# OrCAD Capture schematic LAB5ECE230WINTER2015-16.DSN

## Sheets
1 bit LCD: size A
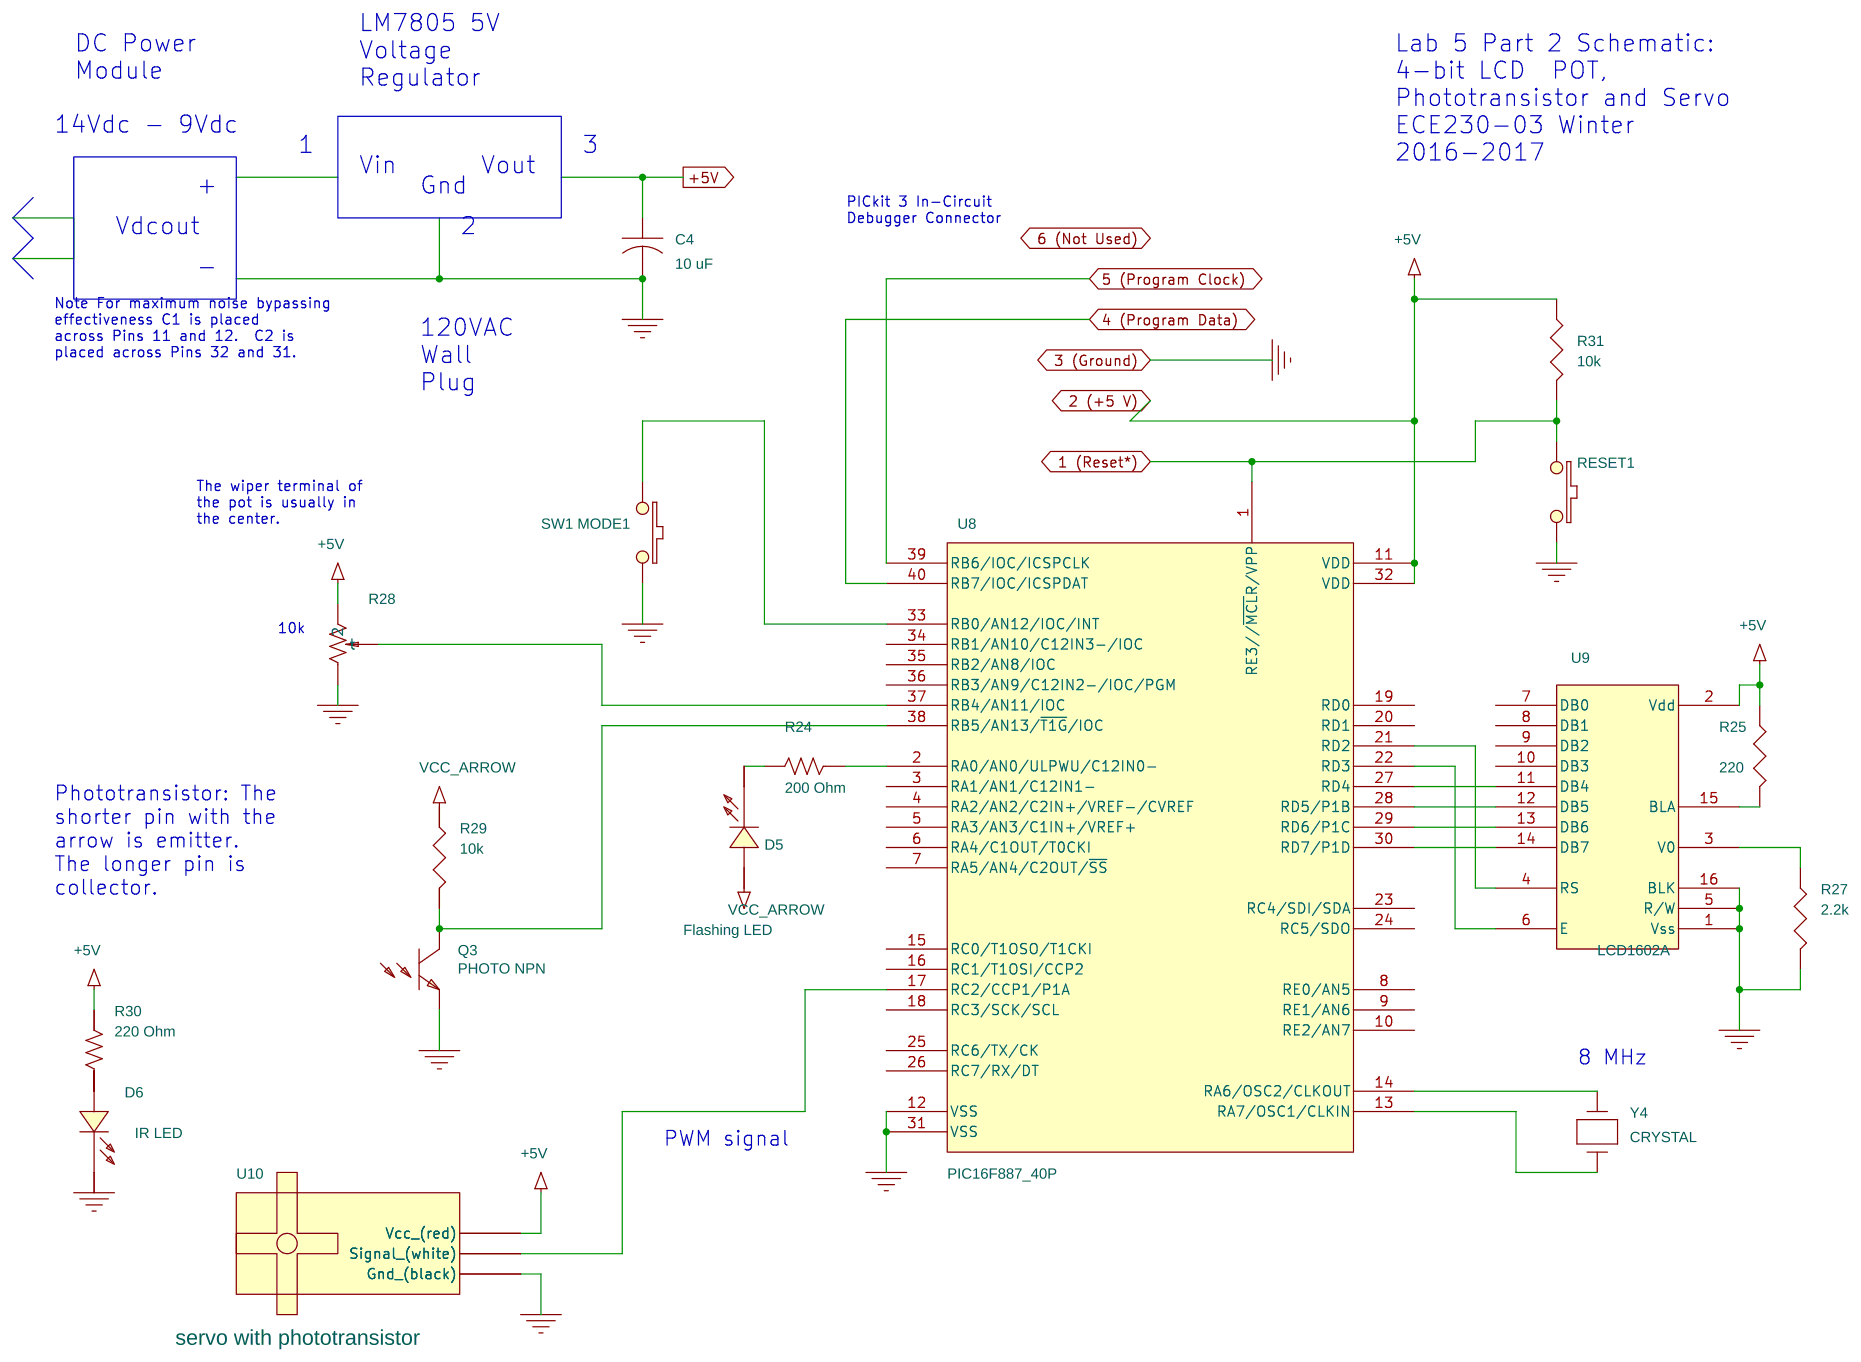
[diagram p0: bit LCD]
2 bit LCD (2): size A
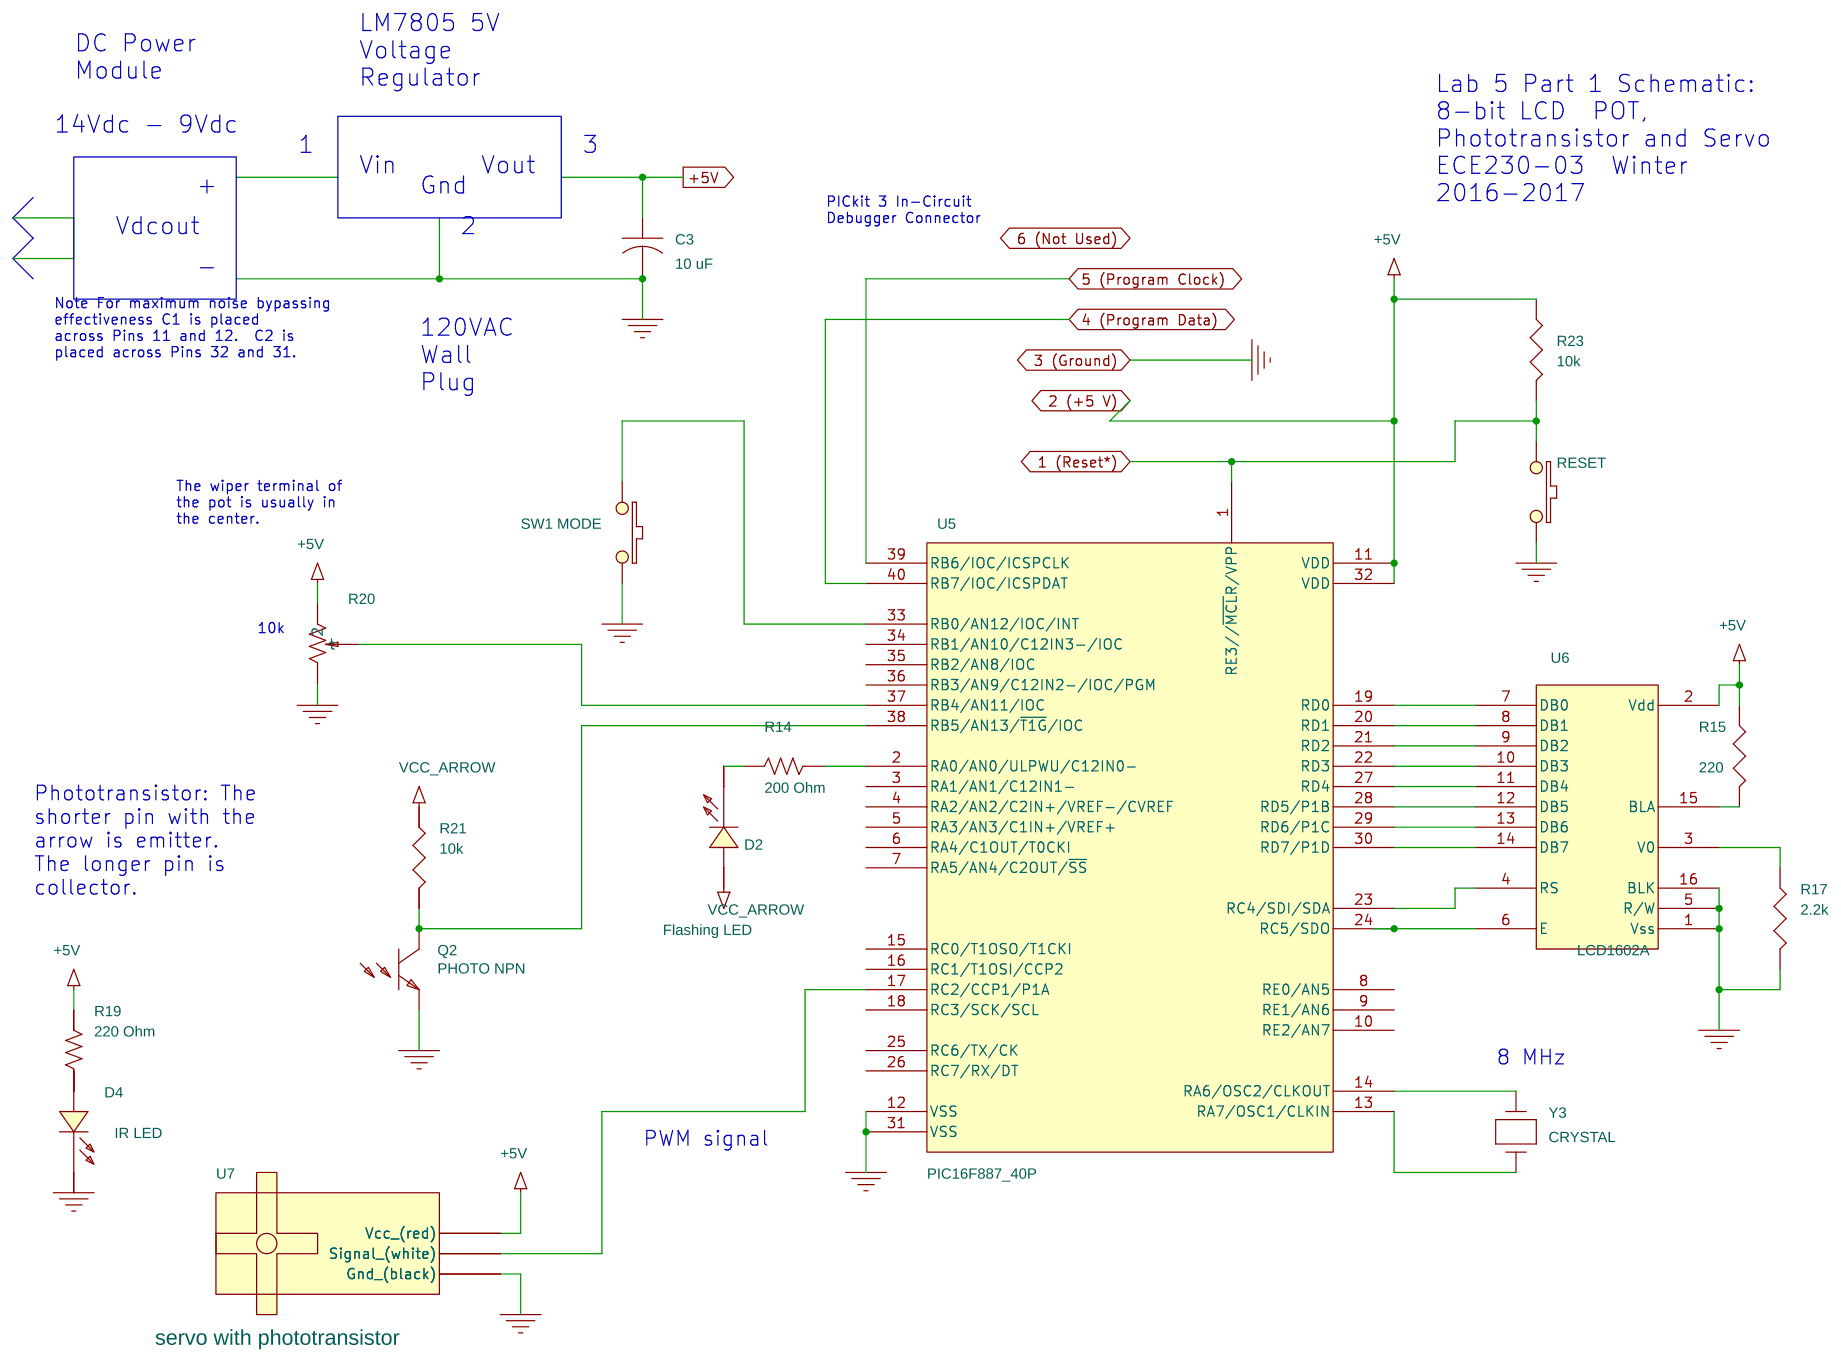
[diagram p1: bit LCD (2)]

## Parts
sheet bit LCD (2)
C3  10 uF
D2  Flashing LED
D4  IR LED
Q2  PHOTO NPN
R14  200 Ohm  [AX/RC05]
R15  220
R17  2.2k
R19  220 Ohm  [AX/RC05]
R20  1K  [VRES10]
R21  10k
R23  10k
RESET  SW PUSHBUTTON
SW1 MODE  SW PUSHBUTTON
U5  PIC16F887_40P
U6  LCD1602A
U7  servo with phototransistor
Y3  CRYSTAL
sheet bit LCD
C4  10 uF
D5  Flashing LED
D6  IR LED
Q3  PHOTO NPN
R24  200 Ohm  [AX/RC05]
R25  220
R27  2.2k
R28  1K  [VRES10]
R29  10k
R30  220 Ohm  [AX/RC05]
R31  10k
RESET1  SW PUSHBUTTON
SW1 MODE1  SW PUSHBUTTON
U8  PIC16F887_40P
U9  LCD1602A
U10  servo with phototransistor
Y4  CRYSTAL

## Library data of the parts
C3 C4 = C
D2 D4-D6 = LED
Q2 Q3 = PHOTO_NPN
R14 R19 R24 R30 = R_v2
R15 R17 R21 R25 R27 R29 = R
R20 R28 = POT_v3
R23 R31 = RESISTOR
RESET RESET1 SW1 MODE SW1 MODE1 = SW_PUSHBUTTON
U5 = PIC16F887_0: ICA_MFR_NAME: Microchip; ICA_PARTNUM: $$48491116942$$PIC16F887-I/P; Part Number: TMP-13
U6 U9 = LCD1602A_4
U7 U10 = servo
Y3 Y4 = CRYSTAL
U8 = PIC16F887_1: ICA_MFR_NAME: Microchip; ICA_PARTNUM: $$48491116942$$PIC16F887-I/P; Part Number: TMP-13

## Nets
+5V: C3.1 C4.1 D2.2(ANODE) D5.2(ANODE) R15.1 R19.2 R20.3(2) R21.1 R23.1 R25.1 R28.3(2) R29.1 R30.2 R31.1 U5.11(VDD) U5.32(VDD) U6.2(Vdd) U7.Vcc_(red) U8.11(VDD) U8.32(VDD) U9.2(Vdd) U10.Vcc_(red)
GND: C3.2 C4.2 D4.2(CATHODE) D6.2(CATHODE) Q2.1(EMITTER) Q3.1(EMITTER) R17.2 R20.1 R27.2 R28.1 RESET.2 RESET1.2 SW1 MODE.2 SW1 MODE1.2 U5.12(VSS) U5.31(VSS) U6.1(Vss) U6.5(R/W) U6.16(BLK) U7.Gnd_(black) U8.12(VSS) U8.31(VSS) U9.1(Vss) U9.5(R/W) U9.16(BLK) U10.Gnd_(black)
1 (Reset*): R23.2 R31.2 RESET.1 RESET1.1 U5.1(RE3//~{MCL}R/VPP) U8.1(RE3//~{MCL}R/VPP)
4 (Program Data): U5.40(RB7/IOC/ICSPDAT) U8.40(RB7/IOC/ICSPDAT)
5 (Program Clock): U5.39(RB6/IOC/ICSPCLK) U8.39(RB6/IOC/ICSPCLK)
N29653: R15.2 U6.15(BLA)
N30165: R14.1 U5.2(RA0/AN0/ULPWU/C12IN0-)
N30259: U5.19(RD0) U6.7(DB0)
N30263: U5.20(RD1) U6.8(DB1)
N30267: U5.21(RD2) U6.9(DB2)
N30271: U5.22(RD3) U6.10(DB3)
N30275: U5.27(RD4) U6.11(DB4)
N30279: U5.28(RD5/P1B) U6.12(DB5)
N30283: U5.29(RD6/P1C) U6.13(DB6)
N30287: U5.30(RD7/P1D) U6.14(DB7)
N30291: U5.23(RC4/SDI/SDA) U6.4(RS)
N30295: U5.24(RC5/SDO) U6.6(E)
N30339: R17.1 U6.3(V0)
N32205: Q2.3(COLLECTOR) R21.2 U5.38(RB5/AN13/~{T1G}/IOC)
N32213: R20.2(t) U5.37(RB4/AN11/IOC)
N32225: U5.17(RC2/CCP1/P1A) U7.Signal_(white)
N32319: D2.1(CATHODE) R14.2
N33018: D4.1(ANODE) R19.1
N1030107: SW1 MODE.1 U5.33(RB0/AN12/IOC/INT)
N1032188: R25.2 U9.15(BLA)
N1032456: R24.1 U8.2(RA0/AN0/ULPWU/C12IN0-)
N1032558: U8.27(RD4) U9.11(DB4)
N1032562: U8.28(RD5/P1B) U9.12(DB5)
N1032566: U8.29(RD6/P1C) U9.13(DB6)
N1032570: U8.30(RD7/P1D) U9.14(DB7)
N1032622: R27.1 U9.3(V0)
N1032780: Q3.3(COLLECTOR) R29.2 U8.38(RB5/AN13/~{T1G}/IOC)
N1032788: R28.2(t) U8.37(RB4/AN11/IOC)
N1032792: U8.17(RC2/CCP1/P1A) U10.Signal_(white)
N1032818: D5.1(CATHODE) R24.2
N1032886: D6.1(ANODE) R30.1
N1032992: SW1 MODE1.1 U8.33(RB0/AN12/IOC/INT)
N1037077: U5.14(RA6/OSC2/CLKOUT) Y3.1
N1037081: U5.13(RA7/OSC1/CLKIN) Y3.2
N1037120: U8.14(RA6/OSC2/CLKOUT) Y4.1
N1037140: U8.13(RA7/OSC1/CLKIN) Y4.2
N1037148: U8.21(RD2) U9.4(RS)
N1037160: U8.22(RD3) U9.6(E)

Not connected (* = marked no-connect by the designer): U5 3(RA1/AN1/C12IN1-) 4(RA2/AN2/C2IN+/VREF-/CVREF) 5(RA3/AN3/C1IN+/VREF+) 6(RA4/C1OUT/T0CKI) 7(RA5/AN4/C2OUT/~{SS}) 8(RE0/AN5) 9(RE1/AN6) 10(RE2/AN7) 15(RC0/T1OSO/T1CKI) 16(RC1/T1OSI/CCP2) 18(RC3/SCK/SCL) 25(RC6/TX/CK) 26(RC7/RX/DT) 34(RB1/AN10/C12IN3-/IOC) 35(RB2/AN8/IOC) 36(RB3/AN9/C12IN2-/IOC/PGM); U8 3(RA1/AN1/C12IN1-) 4(RA2/AN2/C2IN+/VREF-/CVREF) 5(RA3/AN3/C1IN+/VREF+) 6(RA4/C1OUT/T0CKI) 7(RA5/AN4/C2OUT/~{SS}) 8(RE0/AN5) 9(RE1/AN6) 10(RE2/AN7) 15(RC0/T1OSO/T1CKI) 16(RC1/T1OSI/CCP2) 18(RC3/SCK/SCL) 19(RD0) 20(RD1) 23(RC4/SDI/SDA) 24(RC5/SDO) 25(RC6/TX/CK) 26(RC7/RX/DT) 34(RB1/AN10/C12IN3-/IOC) 35(RB2/AN8/IOC) 36(RB3/AN9/C12IN2-/IOC/PGM); U9 7(DB0) 8(DB1) 9(DB2) 10(DB3)

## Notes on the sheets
sheet 1
- LM7805 5V
  Voltage
  Regulator
- DC Power
  Module
- Lab 5 Part 2 Schematic:
  4-bit LCD  POT,
  Phototransistor and Servo
  ECE230-03 Winter
  2016-2017
- 14Vdc - 9Vdc
- 1
- 3
- Vin
- Vout
- +
- Gnd
- PICkit 3 In-Circuit
  Debugger Connector
- Vdcout
- 2
- -
- Note For maximum noise bypassing
  effectiveness C1 is placed
  across Pins 11 and 12.  C2 is
  placed across Pins 32 and 31.
- 120VAC
  Wall
  Plug
- The wiper terminal of
  the pot is usually in
  the center.
- 10k
- Phototransistor: The
  shorter pin with the
  arrow is emitter.
  The longer pin is
  collector.
- 8 MHz
- PWM signal
sheet 2
- LM7805 5V
  Voltage
  Regulator
- DC Power
  Module
- Lab 5 Part 1 Schematic:
  8-bit LCD  POT,
  Phototransistor and Servo
  ECE230-03  Winter
  2016-2017
- 14Vdc - 9Vdc
- 1
- 3
- Vin
- Vout
- +
- Gnd
- PICkit 3 In-Circuit
  Debugger Connector
- Vdcout
- 2
- -
- Note For maximum noise bypassing
  effectiveness C1 is placed
  across Pins 11 and 12.  C2 is
  placed across Pins 32 and 31.
- 120VAC
  Wall
  Plug
- The wiper terminal of
  the pot is usually in
  the center.
- 10k
- Phototransistor: The
  shorter pin with the
  arrow is emitter.
  The longer pin is
  collector.
- 8 MHz
- PWM signal
